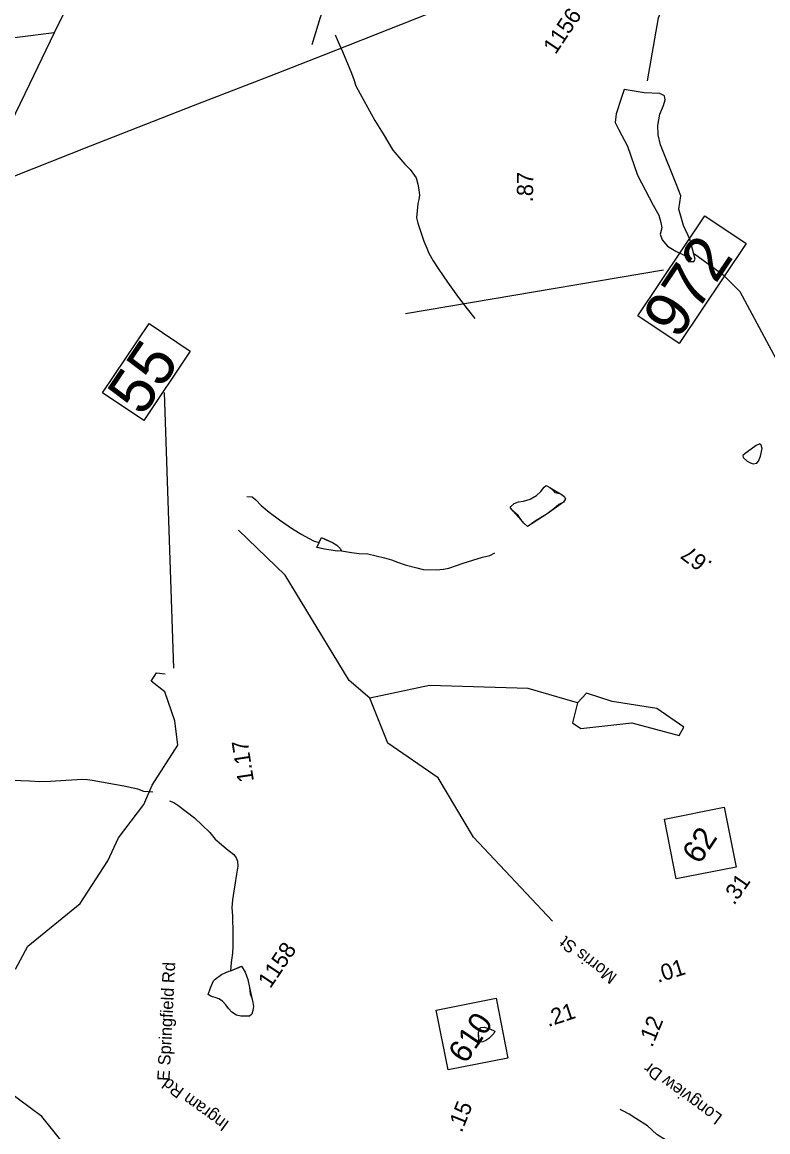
# Model space of a CAD drawing. Extents: x 1716282 to 1717158, y 799307 to 801078.
# Drawn here: x 1716771.4 to 1716854.8, y 799460.6 to 799584.8 of the extents above; entities that cross this region are included whole.
import ezdxf

# ---------------------------------------------------------------- set-up
doc = ezdxf.new("R2010")
doc.units = 0
for name, color, linetype in [('Exist Hydrographic Misc Water Feature', 7, 'Continuous'), ('Exist Hydrographic Pond Under 1500 Sq Ft', 7, 'Continuous'), ('Exist Road Non-System Type 51 Label', 7, 'Continuous'), ('Exist Road Primary NC Mileage Hundredths English Label', 7, 'Continuous'), ('Exist Road Primary NC Service Mileage Hundredths English Label', 7, 'Continuous'), ('Exist Road Primary NC Shield CELL', 7, 'Continuous'), ('Exist Road Primary NC Shield Number Label', 7, 'Continuous'), ('Exist Road Secondary Mileage Hundredths English Label', 7, 'Continuous'), ('Exist Road Secondary Structure Standard Bridge Number Label', 7, 'Continuous'), ('Exist Road Secondary Type 51 Number Label', 7, 'Continuous'), ('Exist Utilities Electrical Transmission Line', 7, 'Continuous')]:
    doc.layers.add(name, color=color, linetype=linetype)

msp = doc.modelspace()

# ---------------------------------------------------------------- linework, layer by layer
at = {"layer": 'Exist Hydrographic Misc Water Feature'}
msp.add_line((1716794.79, 799479.6), (1716794.72, 799478.67), dxfattribs=at)
for points in [[(1716841.35, 799578.26), (1716842.58, 799585.32), (1716843.83, 799588.27), (1716845.87, 799591.27), (1716849.95, 799594.63), (1716851.12, 799597.04), (1716849.41, 799603.49), (1716848.64, 799607.53), (1716848.72, 799611.71), (1716847.13, 799623.06), (1716846.43, 799624.35)], [(1716806.41, 799583.41), (1716806.87, 799582.39), (1716807.24, 799581.54), (1716808.26, 799579.13), (1716808.5, 799578.4), (1716808.73, 799577.71), (1716809.2, 799576.8), (1716810.86, 799573.84), (1716811.77, 799572.34), (1716812.88, 799570.52), (1716814.22, 799568.94), (1716814.81, 799568.36), (1716815.12, 799567.94), (1716815.47, 799567.42), (1716815.67, 799566.69), (1716815.78, 799566.08), (1716815.86, 799565.47), (1716815.76, 799564.97), (1716815.68, 799564.54), (1716815.58, 799563.72), (1716815.5, 799562.94), (1716815.68, 799562.32), (1716816.32, 799560.34), (1716816.66, 799559.54), (1716816.91, 799558.99), (1716817.38, 799558.14), (1716817.95, 799557.26), (1716818.48, 799556.44), (1716818.97, 799555.72), (1716820.11, 799554.16), (1716821.18, 799552.74), (1716822.03, 799551.66)], [(1716873.69, 799527.18), (1716869.62, 799533.48), (1716863.62, 799540.93), (1716859.02, 799543.65), (1716856.02, 799546.58), (1716851.72, 799554.64), (1716849.92, 799556.46), (1716846.61, 799558.86)], [(1716826, 799530.54), (1716826.43, 799530.95), (1716826.91, 799531.15), (1716827.48, 799531.21), (1716828.21, 799531.46), (1716828.93, 799531.84), (1716829.41, 799532.29), (1716829.79, 799532.8), (1716830.03, 799532.99), (1716830.43, 799532.75), (1716830.79, 799532.4), (1716830.97, 799532.2), (1716831.49, 799532.09), (1716831.8, 799531.92), (1716832.04, 799531.76), (1716832.17, 799531.49), (1716831.95, 799531.12), (1716831.45, 799530.86), (1716830.86, 799530.35), (1716830.11, 799529.81), (1716829.36, 799529.33), (1716828.89, 799529.06), (1716828.36, 799528.69), (1716827.93, 799528.38), (1716827.53, 799528.76), (1716827.2, 799529.16), (1716826.89, 799529.62), (1716826.34, 799530.1), (1716826.15, 799530.34), (1716826, 799530.54)], [(1716826, 799530.54), (1716826.43, 799530.95), (1716826.91, 799531.15), (1716827.48, 799531.21), (1716828.21, 799531.46), (1716828.93, 799531.84), (1716829.41, 799532.29), (1716829.79, 799532.8), (1716830.03, 799532.99), (1716830.43, 799532.75), (1716831.8, 799531.92), (1716832.04, 799531.76), (1716832.17, 799531.49), (1716831.95, 799531.12), (1716830.11, 799529.81), (1716827.93, 799528.38), (1716827.53, 799528.76), (1716826.34, 799530.1), (1716826.15, 799530.34), (1716826, 799530.54)], [(1716796.55, 799531.76), (1716797.15, 799531.7), (1716797.56, 799531.38), (1716798.14, 799530.74), (1716799.04, 799529.99), (1716800.2, 799529.13), (1716801.64, 799528.14), (1716802.7, 799527.49), (1716803.45, 799527.08), (1716804.07, 799526.76), (1716804.62, 799526.6)], [(1716810.29, 799509.16), (1716807.98, 799511.17), (1716800.82, 799522.94), (1716795.62, 799527.96)], [(1716807.11, 799525.66), (1716806.64, 799525.64), (1716805.97, 799525.74), (1716805.24, 799525.86), (1716804.61, 799526.01), (1716804.37, 799526.03), (1716804.62, 799526.6)], [(1716807.11, 799525.66), (1716806.64, 799525.64), (1716805.97, 799525.74), (1716805.24, 799525.86), (1716804.37, 799526.03), (1716804.62, 799526.6)], [(1716804.62, 799526.6), (1716804.89, 799527.15), (1716805.42, 799526.9), (1716806.13, 799526.59), (1716806.6, 799526.3), (1716806.98, 799525.93), (1716807.11, 799525.66)], [(1716804.62, 799526.6), (1716804.89, 799527.15), (1716806.13, 799526.59), (1716806.6, 799526.3), (1716806.98, 799525.93), (1716807.11, 799525.66)], [(1716807.11, 799525.66), (1716808.25, 799525.49), (1716809.11, 799525.36), (1716810.08, 799525.33), (1716811.92, 799524.88), (1716812.73, 799524.64), (1716813.38, 799524.4), (1716814.23, 799524.11), (1716815.57, 799523.75), (1716816.27, 799523.59), (1716817.7, 799523.53), (1716818.52, 799523.6), (1716819.13, 799523.71), (1716819.97, 799524.02), (1716820.74, 799524.27), (1716822.88, 799524.94), (1716823.7, 799525.16), (1716824.27, 799525.43)], [(1716785.03, 799497.29), (1716785.96, 799499.44), (1716788.84, 799503.9), (1716788.49, 799506.63), (1716787.35, 799509.9), (1716785.84, 799511.07), (1716786.43, 799512), (1716787.41, 799511.9)], [(1716833.52, 799508.67), (1716827.99, 799510.24), (1716816.98, 799510.59), (1716810.29, 799509.16)], [(1716830.71, 799484.23), (1716821.89, 799493.62), (1716817.95, 799500.27), (1716812.29, 799504.13), (1716810.29, 799509.16)], [(1716786.03, 799498.66), (1716785.03, 799498.74), (1716784.33, 799499), (1716782.79, 799499.32), (1716779.23, 799499.96), (1716778.71, 799500.03), (1716778.21, 799500.06), (1716776.31, 799499.96), (1716774.58, 799499.84), (1716773.37, 799499.82), (1716772.25, 799499.88), (1716770.3, 799499.95), (1716769.37, 799499.78), (1716768.79, 799499.75), (1716768.13, 799499.82)], [(1716770.68, 799478.84), (1716772.03, 799481.42), (1716777.91, 799486.19), (1716781.01, 799490.96), (1716782.17, 799493.53), (1716785.03, 799497.29)], [(1716787.9, 799497.69), (1716788.37, 799497.51), (1716788.83, 799497.2), (1716790.7, 799495.78), (1716792.39, 799494.14), (1716793.01, 799493.4), (1716793.71, 799492.78), (1716794.27, 799492.32), (1716795.1, 799491.68), (1716795.34, 799491.31), (1716795.5, 799490.92), (1716795.52, 799490.38), (1716795.39, 799489.48), (1716795.2, 799488.28), (1716795.07, 799487.56), (1716794.95, 799486.62), (1716794.88, 799485.75), (1716794.92, 799484.78), (1716794.97, 799482.85), (1716794.99, 799481.43), (1716794.95, 799480.65), (1716794.79, 799479.6)], [(1716794.72, 799478.67), (1716795.2, 799478.86), (1716795.57, 799479), (1716795.94, 799479.17), (1716796.37, 799478.52), (1716796.64, 799477.67), (1716796.84, 799476.79), (1716796.93, 799476.1), (1716797.05, 799475.71), (1716797.22, 799475.13), (1716797.29, 799474.66), (1716797.2, 799474.23), (1716797.09, 799473.81), (1716796.84, 799473.6), (1716796.34, 799473.59), (1716795.88, 799473.59), (1716795.4, 799473.7), (1716794.86, 799474.04), (1716794.47, 799474.45), (1716794.18, 799474.85), (1716793.81, 799475.28), (1716793.41, 799475.52), (1716792.98, 799475.67), (1716792.7, 799475.76), (1716792.52, 799475.81), (1716792.22, 799475.99), (1716792.47, 799476.76), (1716792.82, 799477.54), (1716792.99, 799477.74), (1716793.71, 799478.23), (1716794.54, 799478.61), (1716794.72, 799478.67)], [(1716794.72, 799478.67), (1716795.94, 799479.17), (1716796.37, 799478.52), (1716796.64, 799477.67), (1716796.84, 799476.79), (1716797.22, 799475.13), (1716797.29, 799474.66), (1716797.2, 799474.23), (1716797.09, 799473.81), (1716796.84, 799473.6), (1716796.34, 799473.59), (1716795.88, 799473.59), (1716795.4, 799473.7), (1716794.86, 799474.04), (1716794.47, 799474.45), (1716794.18, 799474.85), (1716793.81, 799475.28), (1716793.41, 799475.52), (1716792.98, 799475.67), (1716792.7, 799475.76), (1716792.52, 799475.81), (1716792.22, 799475.99), (1716792.47, 799476.76), (1716792.82, 799477.54), (1716792.99, 799477.74), (1716793.71, 799478.23), (1716794.54, 799478.61), (1716794.72, 799478.67)], [(1716822.67, 799472.33), (1716823.08, 799472.36), (1716823.7, 799472.18), (1716824.29, 799471.92), (1716824.16, 799471.63), (1716823.61, 799471.08), (1716823.28, 799470.85), (1716822.93, 799470.71), (1716822.6, 799470.69), (1716822.49, 799470.83), (1716822.5, 799471.25), (1716822.44, 799471.74), (1716822.67, 799472.33)], [(1716822.67, 799472.33), (1716823.08, 799472.36), (1716823.7, 799472.18), (1716824.29, 799471.92), (1716824.16, 799471.63), (1716823.61, 799471.08), (1716823.28, 799470.85), (1716822.93, 799470.71), (1716822.6, 799470.69), (1716822.49, 799470.83), (1716822.44, 799471.74), (1716822.67, 799472.33)], [(1716769.43, 799412.52), (1716772.52, 799419.19), (1716774.48, 799422.24), (1716775.39, 799425.28), (1716781.89, 799434.58), (1716783, 799438.82), (1716782.75, 799441.46), (1716780.88, 799445.09), (1716780.45, 799451.53), (1716777.57, 799456.13), (1716776.22, 799459.11), (1716773.61, 799462.35), (1716768.36, 799466.22)], [(1716852.78, 799455.19), (1716851.04, 799456.11), (1716848.91, 799457.21), (1716847.94, 799457.7), (1716846.91, 799458.09), (1716845.38, 799458.78), (1716843.48, 799459.65), (1716842.41, 799460.35), (1716841.34, 799461.29), (1716840.05, 799462.14), (1716839.29, 799462.62), (1716838.65, 799462.96), (1716838.28, 799463.14)]]:
    msp.add_lwpolyline(points, dxfattribs=at)
at = {"layer": 'Exist Hydrographic Pond Under 1500 Sq Ft'}
for points in [[(1716840.98, 799576.94), (1716838.74, 799577.28), (1716838.41, 799576.29), (1716837.86, 799574.57), (1716837.72, 799573.59), (1716838.15, 799572.78), (1716839.13, 799570.97), (1716840.25, 799567.7), (1716841.97, 799564.36), (1716842.61, 799563.24), (1716842.85, 799562.42), (1716842.95, 799561.8), (1716842.75, 799561.09), (1716842.99, 799560.47), (1716843.58, 799559.75), (1716844.52, 799559.21), (1716845.6, 799558.67), (1716846.12, 799558.05), (1716846.54, 799558.05), (1716846.68, 799558.32), (1716846.1, 799560.53), (1716845.38, 799562.08), (1716844.87, 799563.91), (1716845.08, 799565.4), (1716844.54, 799566.74), (1716842.81, 799571.11), (1716842.53, 799572.23), (1716842.49, 799573.28), (1716842.72, 799574.53), (1716843.14, 799575.5), (1716843.34, 799576.16), (1716843.26, 799576.59), (1716842.73, 799576.84), (1716840.98, 799576.94)], [(1716852.95, 799537.05), (1716852.26, 799536.56), (1716852.02, 799536.32), (1716852.06, 799536.11), (1716852.5, 799535.71), (1716852.95, 799535.47), (1716853.18, 799535.39), (1716853.56, 799535.48), (1716853.77, 799535.71), (1716853.98, 799536.25), (1716854.19, 799537.12), (1716854.08, 799537.48), (1716853.92, 799537.64), (1716853.5, 799537.44), (1716852.95, 799537.05)], [(1716833.52, 799508.67), (1716832.97, 799506.4), (1716833.88, 799505.79), (1716839.6, 799506.41), (1716844.89, 799505), (1716845.43, 799505.94), (1716842.4, 799508.01), (1716837.38, 799508.8), (1716834.54, 799509.72), (1716833.52, 799508.67)]]:
    msp.add_lwpolyline(points, dxfattribs=at)
at = {"layer": 'Exist Road Primary NC Shield CELL'}
for points in [[(1716844.57, 799488.94), (1716843.24, 799495.64), (1716849.94, 799496.97), (1716851.27, 799490.27)], [(1716819.05, 799467.56), (1716817.72, 799474.26), (1716824.42, 799475.58), (1716825.74, 799468.88)]]:
    msp.add_lwpolyline(points, close=True, dxfattribs=at)
at = {"layer": 'Exist Road Secondary Structure Standard Bridge Number Label'}
for p, q in [((1716803.83, 799582.34), (1716811.93, 799608.72)), ((1716814.27, 799552.23), (1716843.13, 799557.1)), ((1716788.37, 799512.55), (1716787.33, 799543.4))]:
    msp.add_line(p, q, dxfattribs=at)
for points in [[(1716840.27, 799551.98), (1716847.76, 799563.17), (1716852.39, 799560.07), (1716844.9, 799548.88)], [(1716780.41, 799543.35), (1716785.6, 799551.12), (1716790.21, 799548.03), (1716785.01, 799540.27)]]:
    msp.add_lwpolyline(points, close=True, dxfattribs=at)
at = {"layer": 'Exist Utilities Electrical Transmission Line'}
for points in [[(1716806.6, 799651), (1716806.76, 799648.57), (1716802.69, 799640.01), (1716796.73, 799627.95), (1716794, 799622.61), (1716790.62, 799615.93), (1716786.79, 799608.11), (1716782.32, 799598.83), (1716779.17, 799592.17), (1716775, 799583.63)], [(1716871.62, 799607.49), (1716864.93, 799604.82), (1716856.66, 799601.62), (1716853.03, 799600.07), (1716845.73, 799597.25), (1716836.15, 799593.5), (1716828.94, 799590.66), (1716822.85, 799588.2), (1716813.74, 799584.53), (1716805.03, 799581.09), (1716799.02, 799578.75), (1716790.54, 799575.48), (1716779.03, 799570.95), (1716768.37, 799566.75), (1716766.87, 799567.43)], [(1716775, 799583.63), (1716766.67, 799582.61), (1716762.66, 799578.44)], [(1716775, 799583.63), (1716772.22, 799577.9), (1716768.49, 799570.26), (1716766.87, 799567.43)]]:
    msp.add_lwpolyline(points, dxfattribs=at)

# ---------------------------------------------------------------- texts
at = {"layer": 'Exist Road Non-System Type 51 Label'}
for s, height, rotation, p in [('Morris St', 1.377, 142.8194, (1716838.05, 799478.18)), ('E Springfield Rd', 1.3775, 87.2138, (1716787.89, 799466.31)), ('Longview Dr', 1.3775, 143.682, (1716849.83, 799462.45)), ('Ingram Rd', 1.377, 143.8744, (1716794.67, 799461.72))]:
    msp.add_text(s, height=height, rotation=rotation, dxfattribs=at).set_placement(p)
at = {"layer": 'Exist Road Primary NC Mileage Hundredths English Label'}
for s, rotation, p in [('.31', 55.2619, (1716851.03, 799485.93)), ('.01', 17.5452, (1716842.52, 799477.3)), ('.21', 18.2368, (1716830.25, 799472.36)), ('.15', 68.2798, (1716820.57, 799460.47))]:
    msp.add_text(s, height=1.812, rotation=rotation, dxfattribs=at).set_placement(p)
at = {"layer": 'Exist Road Primary NC Service Mileage Hundredths English Label'}
msp.add_text('.12', height=1.812, rotation=67.5952, dxfattribs=at).set_placement((1716841.87, 799470.01))
at = {"layer": 'Exist Road Primary NC Shield Number Label'}
for s, p in [('62', (1716847.16, 799490.48)), ('610', (1716821.01, 799468.15))]:
    msp.add_text(s, height=2.537, rotation=56.2051, dxfattribs=at).set_placement(p)
at = {"layer": 'Exist Road Secondary Mileage Hundredths English Label'}
for s, rotation, p in [('.87', 89.2996, (1716828.54, 799564.68)), ('.67', 142.9372, (1716848.7, 799524.34)), ('1.17', 98.7366, (1716797.34, 799499.9))]:
    msp.add_text(s, height=1.813, rotation=rotation, dxfattribs=at).set_placement(p)
at = {"layer": 'Exist Road Secondary Structure Standard Bridge Number Label'}
for s, p in [('972', (1716844.76, 799549.19)), ('55', (1716784.88, 799540.58))]:
    msp.add_text(s, height=5.075, rotation=56.2051, dxfattribs=at).set_placement(p)
at = {"layer": 'Exist Road Secondary Type 51 Number Label'}
for s, p in [('1156', (1716831.06, 799581.14)), ('1158', (1716799.16, 799476.59))]:
    msp.add_text(s, height=1.812, rotation=56.2051, dxfattribs=at).set_placement(p)

doc.saveas('drawing.dxf')
